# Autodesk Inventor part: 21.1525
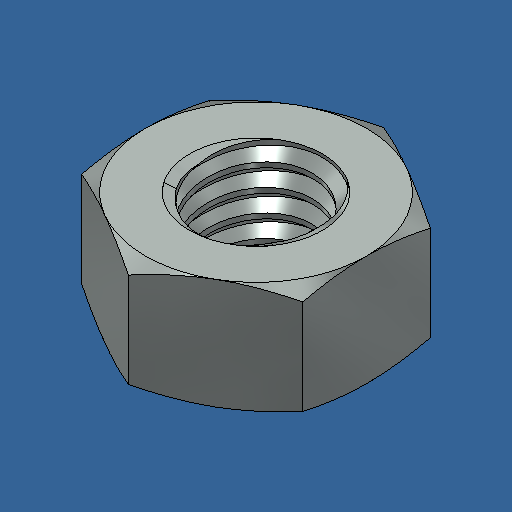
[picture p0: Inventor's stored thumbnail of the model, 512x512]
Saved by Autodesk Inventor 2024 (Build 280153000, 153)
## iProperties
Created: 2012-02
Part Number: 21.1525
Document SubType Name: Modeling
Designer: Administrator
Density: 7.85 g/cm^3
Material: Steel
Mass: 2.42169 g
Surface Area: 4.15922 cm^2
Volume: 0.308495 cm^3
Description: M6 HEX NUT
Appearance: Zinc
Translation Standard: STEP AP203
FileName: 90591A151.step
PreProcessor: SolidWorks 2007
PostProcessor: Build: 236a, Release: 2009 RTM - Date: Fri 02/22/2008
Sent Units: MM
Uncertainty: 1e-05
Author: Administrator
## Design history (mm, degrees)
feature "Base1"
body "Solid1"
